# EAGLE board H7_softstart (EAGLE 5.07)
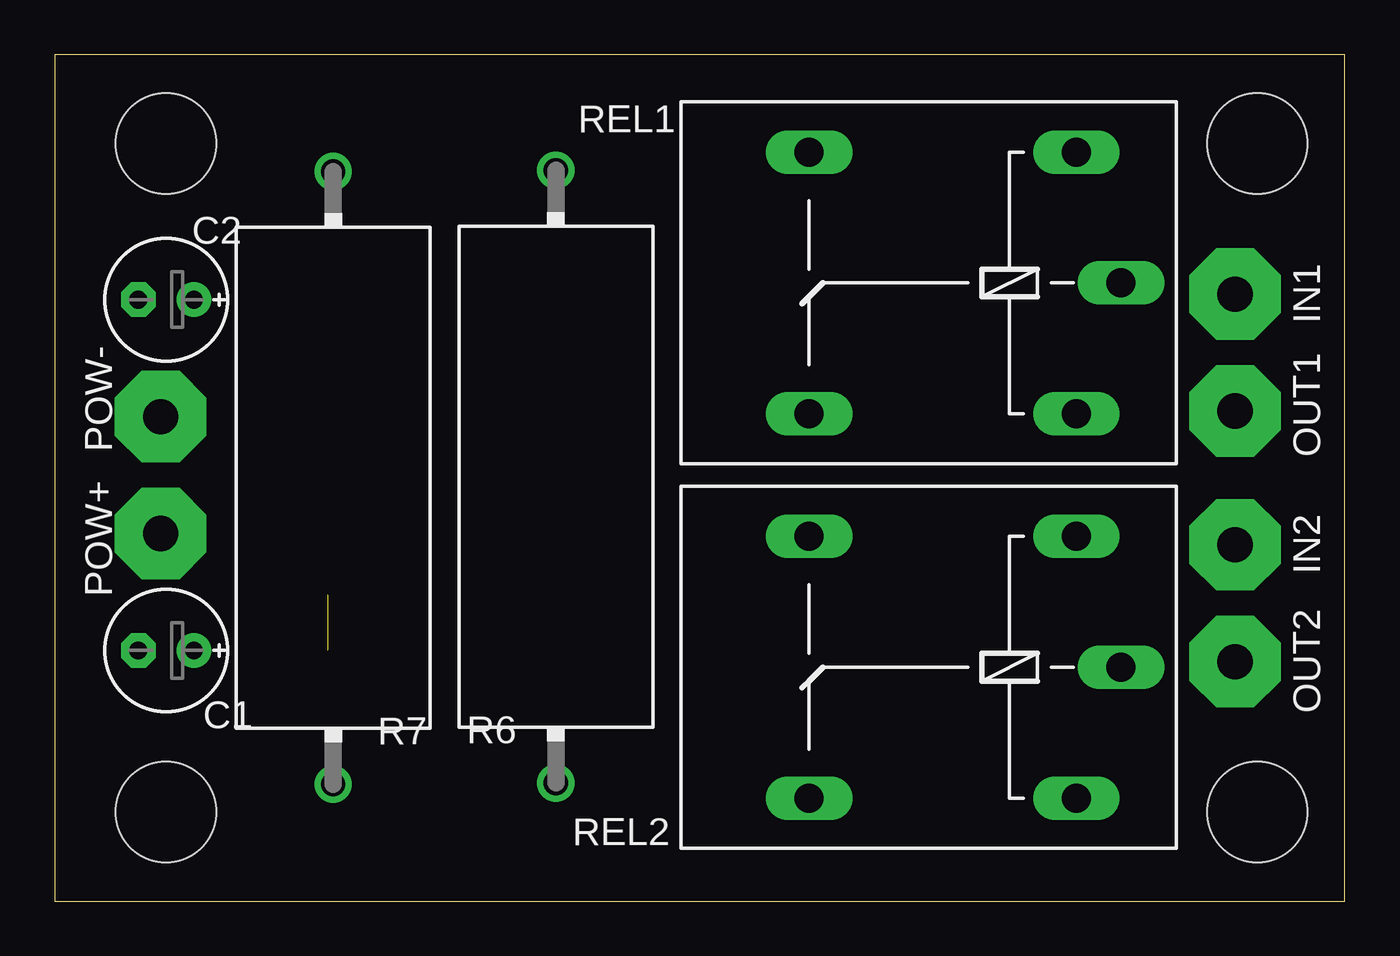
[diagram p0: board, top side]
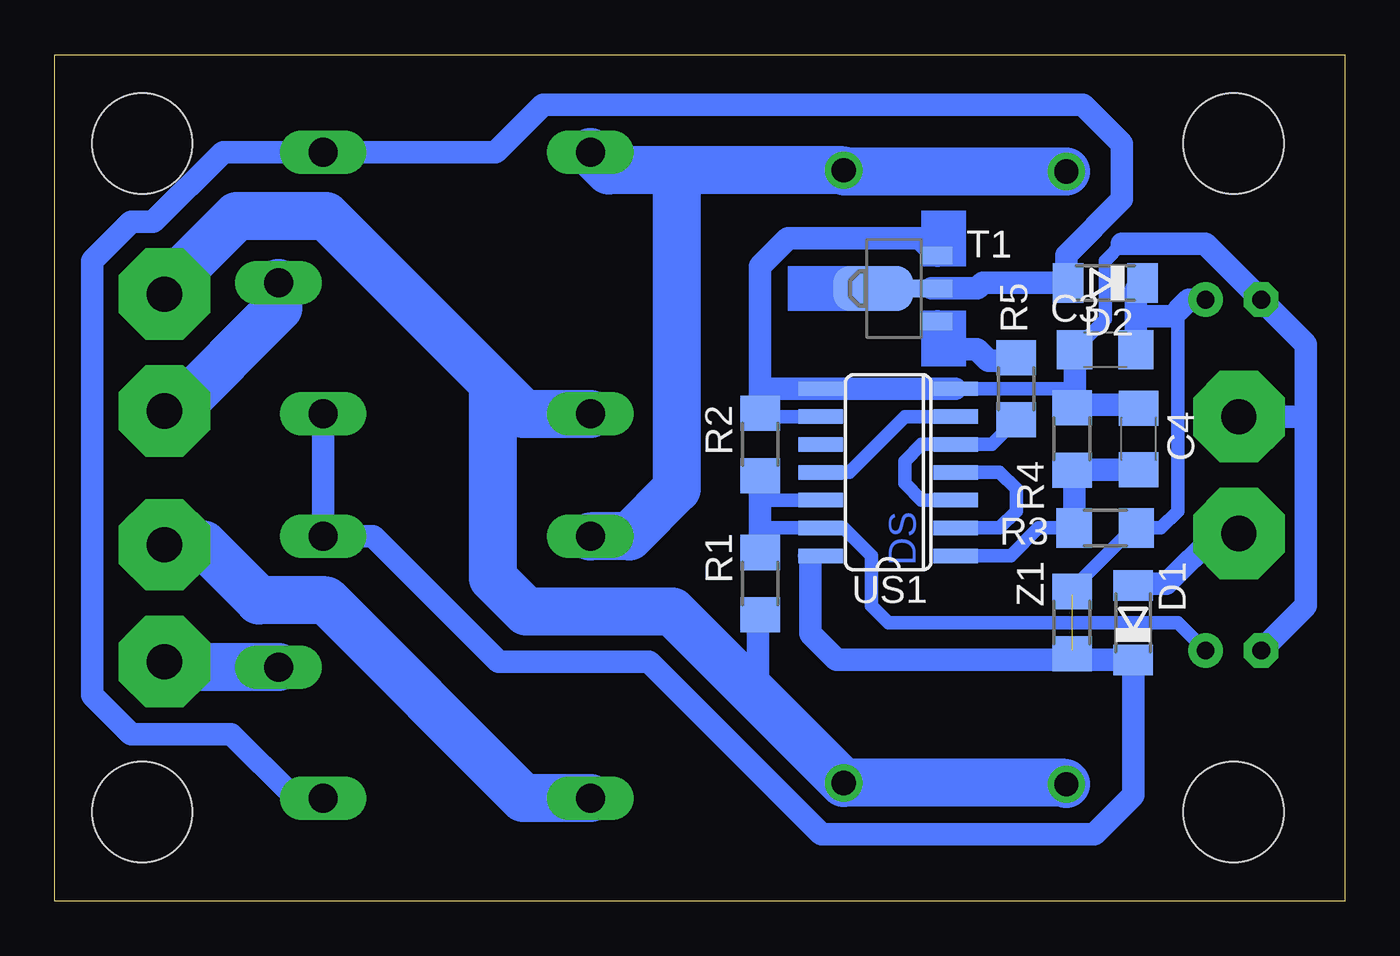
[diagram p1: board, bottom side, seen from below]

Size 58.85 x 38.6 mm. Coordinates in mm from the lower left corner, seen from the top.
Outline: 0,0 58.85,0 58.85,38.6 0,38.6 0,0
Copper layers (1*16): Top 0.035mm / dielectric 1.5mm / Bottom 0.035mm
Design rules "default": minimum track width 10mil, minimum drill 24mil, track to track 8mil, track to pad 8mil, pad to pad 8mil, via to via 8mil, smd to smd 8mil, copper to edge 40mil, drill to drill 8mil, minimum pad ring 10mil, minimum via ring 8mil, stop-mask expansion 4mil, vias tented up to drill 0mil, thermal gap 10mil
Holes 4.57 mm at 5.08,34.54 54.86,34.54 54.86,4.06 5.08,4.06

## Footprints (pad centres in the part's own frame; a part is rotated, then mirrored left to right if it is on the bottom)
E2,5-6E = drill 0.813 pad 1.575 round: + -1.27,0 | drill 0.813 pad 1.575 octagon: - 1.27,0
C1206 = smd 1.6 x 1.8: 1 -1.4,0; 2 1.4,0
SOD80C = smd 1.4 x 1.8: A 1.7,0; C -1.7,0
4,16O1,6 = drill 1.6 pad 4.166 octagon: 1 0,0
R1206 = smd 1.6 x 1.803: 1 -1.422,0; 2 1.422,0
HPS923 = drill 1.1 pad 1.7 round: 1 -13.97,0; 2 13.97,0
G5LE = drill 1.321 long: 1 -7.493,-5.969; 2 -7.493,5.969; O 4.699,5.969; P -9.525,0; S 4.699,-5.969
SOT89-BCE = smd 0.8 x 1.4: B -1.499,-1.981; E 1.499,-1.981 | smd 0.8 x 1.9: C 0,-1.727 | smd 2.032 x 3.65: C@1 0,0.94
SO14 = smd 0.66 x 2.032: 1 -3.81,-3.073; 2 -2.54,-3.073; 3 -1.27,-3.073; 4 0,-3.073; 5 1.27,-3.073; 6 2.54,-3.073; 7 3.81,-3.073; 8 3.81,3.073; 9 2.54,3.073; 10 1.27,3.073; 11 0,3.073; 12 -1.27,3.073; 13 -2.54,3.073; 14 -3.81,3.073

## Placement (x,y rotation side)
C1  100uF  [E2,5-6E]  5.08,11.43 180 top
C2  100uF  [E2,5-6E]  5.08,27.43 180 top
C3  1uF  [C1206]  10.92,25.15 180 bottom
C4  1uF  [C1206]  9.4,21.08 90 bottom
D1  1N4007  [SOD80C]  9.65,12.7 90 bottom
D2  1N4148  [SOD80C]  10.92,28.19 180 bottom
IN1  [4,16O1,6]  53.85,27.69 0 top
IN2  [4,16O1,6]  53.85,16.26 0 top
OUT1  [4,16O1,6]  53.85,22.35 0 top
OUT2  [4,16O1,6]  53.85,10.92 0 top
POW+  [4,16O1,6]  4.83,16.76 0 top
POW-  [4,16O1,6]  4.83,22.1 0 top
R1  82k  [R1206]  26.67,14.48 270 bottom
R2  470k  [R1206]  26.67,20.83 270 bottom
R3  100k  [R1206]  10.92,17.02 0 bottom
R4  470k  [R1206]  12.45,21.08 270 bottom
R5  10k  [R1206]  14.99,23.37 270 bottom
R6  3R9  [HPS923]  22.86,19.36 270 top
R7  3R9  [HPS923]  12.7,19.3 270 top
REL1  [G5LE]  39.12,28.19 180 top
REL2  [G5LE]  39.12,10.67 180 top
T1  BCP56  [SOT89-BCE]  20.57,27.94 90 bottom
US1  4093D  [SO14]  20.83,19.56 90 bottom
Z1  zw  [R1206]  12.45,12.7 270 bottom

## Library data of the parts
C1-C4 R1-R5 Z1 = rcl
D1 D2 = diode
IN1 IN2 OUT1 OUT2 POW+ POW- = wirepad
R6 R7 = resistor-power
REL1 REL2 = relay
T1 = transistor
US1 = 40xx

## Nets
GND: C1.- C2.- C3.2 C4.2 POW-.1 R2.1 R4.1 T1.E US1.7 US1.8 US1.9
N$1: US1.6 US1.11
N$2: R5.2 US1.3 US1.5
N$3: US1.2 US1.4
N$4: C4.1 R3.1 R4.2 US1.1
N$5: OUT1.1 REL1.P
N$6: R5.1 T1.B
N$7: D2.A REL1.1 REL2.2 T1.C
N$8: C2.+ C3.1 D1.C D2.C R3.2 REL1.2 REL2.1 US1.14
N$9: IN2.1 REL2.O
N$10: D1.A POW+.1
N$11: C1.+ R1.1 R2.2 US1.12 US1.13
N$12: R6.1 R7.1 REL1.S REL2.S
N$13: OUT2.1 REL2.P
N$15: IN1.1 R1.2 R6.2 R7.2 REL1.O

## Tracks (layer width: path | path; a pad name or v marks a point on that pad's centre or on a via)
GND
  Bottom 0.61: US1.9 26.57,22.1 R2.1 | R4.1 12.32,22.63 12.32,23.37 US1.7 | 9.54,22.63 C4.2 | C3.2 10.92,26.55 10.92,29.21 10.16,29.97
  Bottom 1.016: 26.67,23.37 US1.8 US1.7 | 26.67,23.37 R2.1 | 26.67,23.37 26.67,28.96 25.4,30.23 19.38,30.23 T1.E | 10.16,29.97 6.35,29.97 C2.- 1.78,25.4 1.78,22.1 | C3.2 12.32,23.37 | 12.32,22.63 9.54,22.63 | 1.78,22.1 1.78,13.46 C1.- | 1.78,22.1 POW-.1
N$1
  Bottom 0.61: US1.11 22.61,19.56 20.07,22.1 US1.6
N$2
  Bottom 0.61: US1.3 19.3,18.29 20.07,19.05 20.07,20.07 19.3,20.83 US1.5 16.1,20.83 R5.2
N$3
  Bottom 0.61: US1.2 15.75,17.02 14.99,17.78 14.99,18.8 15.75,19.56 US1.4
N$4
  Bottom 0.61: 12.42,19.68 R4.2 12.34,19.56 | US1.1 15.24,15.75 13.97,17.02 R3.1
  Bottom 1.016: C4.1 12.42,19.68 | 12.34,19.56 R3.1
N$5
  Bottom 2.184: REL1.P 48.64,27.05 53.34,22.35 OUT1.1
N$6
  Bottom 0.61: R5.1 15.14,24.64
  Bottom 1.016: T1.B 18.54,25.4 18.54,25.17 16.79,25.17 16.26,24.64 15.14,24.64
N$7
  Bottom 1.016: T1.C 16.76,27.94 16.51,28.19 D2.A 12.7,28.27 12.7,29.46 10.16,32 10.16,34.54 11.94,36.32 36.58,36.32 38.73,34.16 REL1.1 51.18,34.16 54.36,30.99 55.37,30.99 57.15,29.21 57.15,9.4 55.37,7.62 50.8,7.62 48.01,4.83 46.74,4.83 REL2.2
N$8  (1 unrouted)
  Bottom 0.61: 24.38,15.49 24.64,15.75 US1.14 | 12.45,13.97 12.45,14.22 9.8,16.87 9.65,16.87 R3.2 8.38,17.02 7.62,17.78 7.62,26.92 7.87,26.67 | 12.45,11 12.45,11.43 | 9.52,27.89 D2.C
  Bottom 1.016: 7.62,26.92 7.11,27.43 C2.+ | 24.38,15.49 24.38,12.19 23.19,11 12.45,11 D1.C 9.65,4.83 11.43,3.05 23.88,3.05 31.75,10.92 38.61,10.92 44.32,16.64 REL2.1 REL1.2 | 9.52,26.67 C3.1 | 9.52,26.67 9.52,27.89 | 7.87,26.67 9.52,26.67
N$9
  Bottom 2.184: IN2.1 52.07,16.26 49.53,13.72 46.48,13.72 37.47,4.7 REL2.O
N$10
  Bottom 0.61: 9.57,14.48 D1.A
  Bottom 1.016: POW+.1 5.84,16.76 8.13,14.48 9.57,14.48
N$11
  Bottom 0.61: R1.1 26.31,17.02 US1.13 22.86,17.02 21.59,15.75 21.59,13.46 20.83,12.7 7.62,12.7 C1.+ | US1.12 26.42,18.29 26.67,18.03
  Bottom 1.016: R1.1 26.67,18.03 R2.2
N$12
  Bottom 2.184: REL2.S 32.64,16.64 30.48,18.8 30.48,33.08 30.73,33.33 | R7.1 22.8,33.27 R6.1 30.73,33.33 | 30.73,33.33 33.58,33.33 REL1.S
N$13
  Bottom 2.184: REL2.P 53.47,10.67 OUT2.1
N$15
  Bottom 1.016: R1.2 26.77,12.96 26.77,9.3
  Bottom 2.184: IN1.1 53.85,27.94 50.55,31.24 46.48,31.24 38.86,23.62 | 38.86,23.62 37.47,22.23 REL1.O | R7.2 12.76,5.39 R6.2 26.77,9.3 30.68,13.21 37.34,13.21 38.86,14.73 38.86,23.62
(copper drawn outside any net)
  shapes: Bottom area x3

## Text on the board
Bottom: DS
